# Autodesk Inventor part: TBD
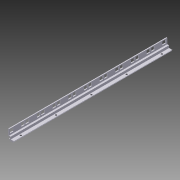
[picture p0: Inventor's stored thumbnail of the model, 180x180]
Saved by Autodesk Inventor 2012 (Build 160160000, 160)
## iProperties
Created: 2004-11
Material: Aluminum-6061
Document SubType Name: Modeling
Designer: Autodesk, Inc.
Manufacturer: Standard
Standards Organization: Custom
Stock Number: 12-109M
Catalog Web Link: http://www.parker.com/ead/cm1.asp?cmid=809
Description: 19" RACK ANGLE
Vendor: PARKER IPS
Part Number: TBD
Mass: 126.265 g
Surface Area: 389.073 cm^2
Volume: 46.5923 cm^3
Density: 2.71 g/cm^3
CAGE: 1LJX3
Dept. ID: Product Design
Description #2: ---
Finish #1: ---
Finish #2: ---
Material ID: ---
Project Number: ---
Author: Autodesk, Inc.
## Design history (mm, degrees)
sketch "Sketch1"
  geometry: L1 (-2.868, 4.096)-(0, 0) reference; L2 (0, 0)-(7.764, 0) reference; L3 (7.764, 0)-(10.632, 4.096) reference; L4 (10.632, 4.096)-(10.632, 4.7) reference; L5 (10.632, 4.7)-(1.732, 4.7) reference; L6 (1.732, 4.7)-(1.732, 11.5) reference; L7 (1.732, 11.5)-(-3.268, 11.5) reference; L8 (-3.268, 11.5)-(-3.268, 27.5) reference; L9 (-3.268, 27.5)-(-5.768, 27.5) reference; L10 (-5.768, 27.5)-(-5.768, 9.5) reference; L11 (-5.768, 9.5)-(0.032, 9.5) reference; L12 (0.032, 9.5)-(0.032, 4.7) reference; L13 (0.032, 4.7)-(-2.868, 4.7) reference; L14 (-2.868, 4.7)-(-2.868, 4.096) reference
  constraints: 28 end point, 6 horizontal, 6 vertical, 16 other
extrude "Extrusion1" new body sketch "Sketch1" taper "d1" = 0 deg; distance "Length" = 448.75 (computed from RackU)
sketch "Sketch2"
  geometry: L1 (8.9, 0)-(0, 0) reference; 2 further points
  constraints: 1 midpoint, 1 vertical alignment
  dimensions: "d2" = 24 distance from line of L1 point (4.45, 24)
hole "Hole1" sketch "Sketch2" at (4.45, 24) diameter "d3" = 4.917; stored, may be unused: countersink angle "d7" = 90 deg, drill point angle "d9" = 118 deg; dims "d4" = 6, "d5" = 4, "d6" = 2, "d8" = 8
pattern_linear "Rectangular Pattern1" dims "d12" = 100
sketch "Sketch3"
  geometry: L1 (3.25, 13.75)-(12.75, 13.75); L2 (12.75, 13.75)-(12.75, 4.25); L3 (12.75, 4.25)-(3.25, 4.25); L4 (3.25, 4.25)-(3.25, 13.75); L5 (8, 13.75)-(8, 4.25); L6 (0, 0)-(0, 16) reference; L7 (3.25, 9)-(12.75, 9); L8 (0, -2)-(448.75, -2) reference
  constraints: 12 end point, 4 midpoint, 2 parallel, 2 perpendicular, 1 horizontal
  dimensions: "d13" = 9.5 distance of L1.end L2.end; "d14" = 8 distance between parallel lines of L5 L6; "d15" = 11 distance between parallel lines of L8 L7
extrude "12-109M" cut sketch "Sketch3" stored distance "d16" = 500; taper "d17" = 0 deg
body "Solid1"
pattern_linear "Rectangular Pattern2" dims "d20" = 31.75, "d23" = 44.45
